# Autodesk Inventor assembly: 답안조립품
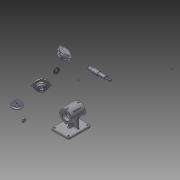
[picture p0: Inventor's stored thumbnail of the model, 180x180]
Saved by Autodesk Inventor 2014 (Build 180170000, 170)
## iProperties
Created: 2015-12
Part Number: 답안조립품
Document SubType Name: Assembly
Designer: basic
Author: basic
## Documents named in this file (11)
- C:\Users\basic\Desktop\451208V1030\답안조립품.iam
- C:\Users\basic\Desktop\451208V1030\V-벨트풀리.ipt
- C:\Users\basic\Desktop\451208V1030\너트 M12x1.25.ipt
- C:\Users\basic\Desktop\451208V1030\베어링 6204.ipt
- C:\Users\basic\Desktop\451208V1030\본체.ipt
- C:\Users\basic\Desktop\451208V1030\볼트 M4 x 12.ipt
- C:\Users\basic\Desktop\451208V1030\오일실.ipt
- C:\Users\basic\Desktop\451208V1030\축.ipt
- C:\Users\basic\Desktop\451208V1030\커버.ipt
- C:\Users\basic\Desktop\451208V1030\커버2.ipt
- C:\Users\basic\Desktop\451208V1030\키(4 x 4 x 12).ipt
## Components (6 placed, 5 different names)
1. V-벨트풀리:2
2. KS B 1012 클래스 1 일반 - 미터 M12x1.25:2
3. KS B 2023 6204 - 20 x 47 x 14:2
4. KS B 2804 D D - 20 32 8:2
5. KS B 1311 (I) 4 x 4 x 12:2
6. KS B 2023 6204 - 20 x 47 x 14:3
